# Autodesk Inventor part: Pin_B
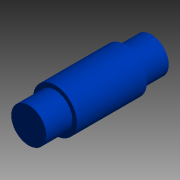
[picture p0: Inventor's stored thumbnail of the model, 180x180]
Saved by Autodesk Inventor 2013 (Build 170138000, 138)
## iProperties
Shininess: 0.0
Length Units: 11272
Angle Units: 11279
Time Units: 11290
Mass Units: 11283
Length Display Precision: 3
Angle Display Precision: 1
Compacted: True
Created: 1999-07
Part Number: Pin_B
Document SubType Name: Modeling
Designer: Administrator
Density: 7.86 g/cm^3
Material: Steel, Mild
Mass: 7.31047 g
Surface Area: 6.05674 cm^2
Volume: 0.930085 cm^3
Density: 0.0
Volumn: 0.0
Area: 0.0
PropertySet Name: Model Information
Control State: 0
Master: False
Checked Out: False
Author: Administrator
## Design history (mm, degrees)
node "y-z Plane"
  node "x-z Plane"
  node "x-y Plane"
node "Extrusion1" dims "d0" = 4.7625, "d1" = 0
  sketch "Sketch1"
    geometry: C1 r 3.175 at (0, 0); 1 further point
    constraints: 1 centre point, 1 coincident
    dimensions: "d7" = 6.35 diameter of C1
node "Extrusion2" dims "d3" = 12.7, "d4" = 0
  sketch "Sketch2"
    geometry: C1 r 3.175 at (0, 0) reference; C2 r 3.969 at (0, 0)
    constraints: 1 centre point, 1 coincident
    dimensions: "d2" = 7.9375 diameter of C2
node "Extrusion3" dims "d5" = 4.7625, "d6" = 0
  sketch "Sketch3"
    geometry: C1 r 3.175 at (0, 0) reference
body "Solid1"
